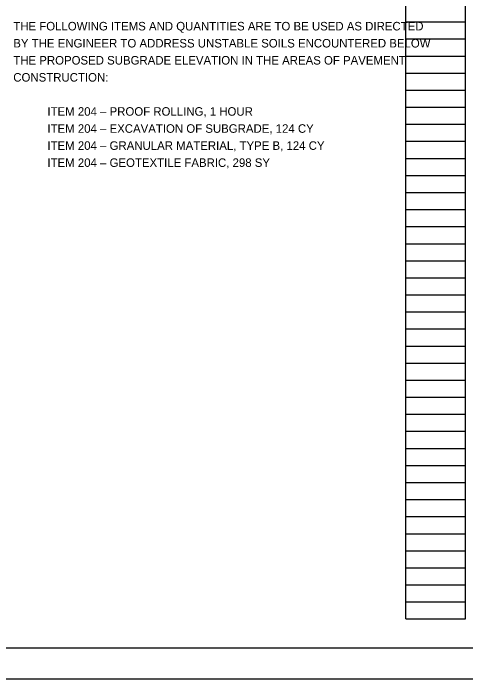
# Model space of a CAD drawing. Extents: x 0 to 34, y 0 to 22.
# Drawn here: x 17.24 to 24.66, y 0 to 10.92 of the extents above; entities that cross this region are included whole.
import ezdxf

# ---------------------------------------------------------------- set-up
doc = ezdxf.new("R2010")
doc.units = 0
for name, color, linetype in [('SH_Border', 7, 'Continuous'), ('SH_Cut_Line', 7, 'Continuous'), ('SH_Data', 7, 'Continuous'), ('SH_Text', 7, 'Continuous')]:
    doc.layers.add(name, color=color, linetype=linetype)

msp = doc.modelspace()

# ---------------------------------------------------------------- linework, layer by layer
at = {"layer": 'SH_Border'}
msp.add_lwpolyline([(1.5, 21.5), (33.5, 21.5), (33.5, 0.5), (1.5, 0.5)], close=True, dxfattribs=at)
at = {"layer": 'SH_Cut_Line'}
msp.add_lwpolyline([(0, 0), (34, 0), (34, 22), (0, 22)], close=True, dxfattribs=at)
at = {"layer": 'SH_Data'}
for p, q in [((23.68, 0.98), (23.68, 21.14)), ((24.66, 0.98), (24.66, 21.14)), ((23.68, 10.78), (24.66, 10.78)), ((23.68, 10.5), (24.66, 10.5)), ((23.68, 10.22), (24.66, 10.22)), ((23.68, 9.94), (24.66, 9.94)), ((23.68, 9.66), (24.66, 9.66)), ((23.68, 9.38), (24.66, 9.38)), ((23.68, 9.1), (24.66, 9.1)), ((23.68, 8.82), (24.66, 8.82)), ((23.68, 8.54), (24.66, 8.54)), ((23.68, 8.26), (24.66, 8.26)), ((23.68, 7.98), (24.66, 7.98)), ((23.68, 7.7), (24.66, 7.7)), ((23.68, 7.42), (24.66, 7.42)), ((23.68, 7.14), (24.66, 7.14)), ((23.68, 6.86), (24.66, 6.86)), ((23.68, 6.58), (24.66, 6.58)), ((23.68, 6.3), (24.66, 6.3)), ((23.68, 6.02), (24.66, 6.02)), ((23.68, 5.74), (24.66, 5.74)), ((23.68, 5.46), (24.66, 5.46)), ((23.68, 5.18), (24.66, 5.18)), ((23.68, 4.9), (24.66, 4.9)), ((23.68, 4.62), (24.66, 4.62)), ((23.68, 4.34), (24.66, 4.34)), ((23.68, 4.06), (24.66, 4.06)), ((23.68, 3.78), (24.66, 3.78)), ((23.68, 3.5), (24.66, 3.5)), ((23.68, 3.22), (24.66, 3.22)), ((23.68, 2.94), (24.66, 2.94)), ((23.68, 2.66), (24.66, 2.66)), ((23.68, 2.38), (24.66, 2.38)), ((23.68, 2.1), (24.66, 2.1)), ((23.68, 1.82), (24.66, 1.82)), ((23.68, 1.54), (24.66, 1.54)), ((23.68, 1.26), (24.66, 1.26)), ((23.68, 0.98), (24.66, 0.98))]:
    msp.add_line(p, q, dxfattribs=at)

# ---------------------------------------------------------------- texts
at = {"layer": 'SH_Text'}
for s, p in [('THE FOLLOWING ITEMS AND QUANTITIES ARE TO BE USED AS DIRECTED ', (17.24, 10.64)), ('BY THE ENGINEER TO ADDRESS UNSTABLE SOILS ENCOUNTERED BELOW ', (17.24, 10.36)), ('THE PROPOSED SUBGRADE ELEVATION IN THE AREAS OF PAVEMENT ', (17.24, 10.08)), ('CONSTRUCTION:', (17.24, 9.8)), ('ITEM 204 – PROOF ROLLING, 1 HOUR', (17.8, 9.24)), ('ITEM 204 – EXCAVATION OF SUBGRADE, 124 CY', (17.8, 8.96)), ('ITEM 204 – GRANULAR MATERIAL, TYPE B, 124 CY', (17.8, 8.68)), ('ITEM 204 – GEOTEXTILE FABRIC, 298 SY', (17.8, 8.4))]:
    msp.add_text(s, height=0.14, dxfattribs=at).set_placement(p)

doc.saveas('drawing.dxf')
